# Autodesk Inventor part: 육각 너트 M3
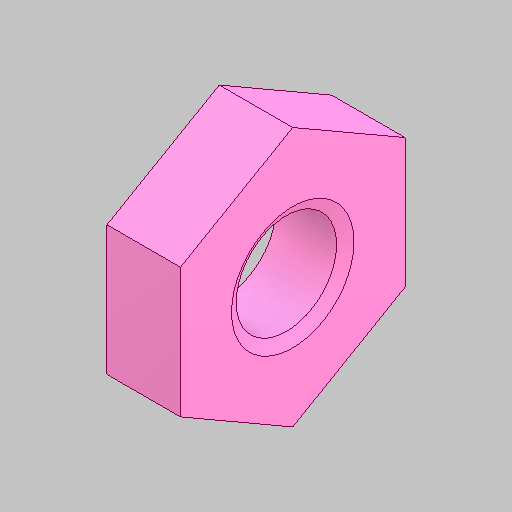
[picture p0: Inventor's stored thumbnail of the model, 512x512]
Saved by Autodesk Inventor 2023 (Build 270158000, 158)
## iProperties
Created: 2025-09
Part Number: 육각 너트 M3
Material: 강철, 연강
Description: 6각 너트 및 6각 가는 너트 - 모따기 안된
Document SubType Name: Modeling
Designer: home
Density: 7.85 g/cm^3
Appearance: 기본값
Author: jhkim
Sending System: Autodesk Inventor 2026
Preprocessor: ST-DEVELOPER v20.1
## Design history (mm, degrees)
feature "Solid1"
node "솔리드1"
